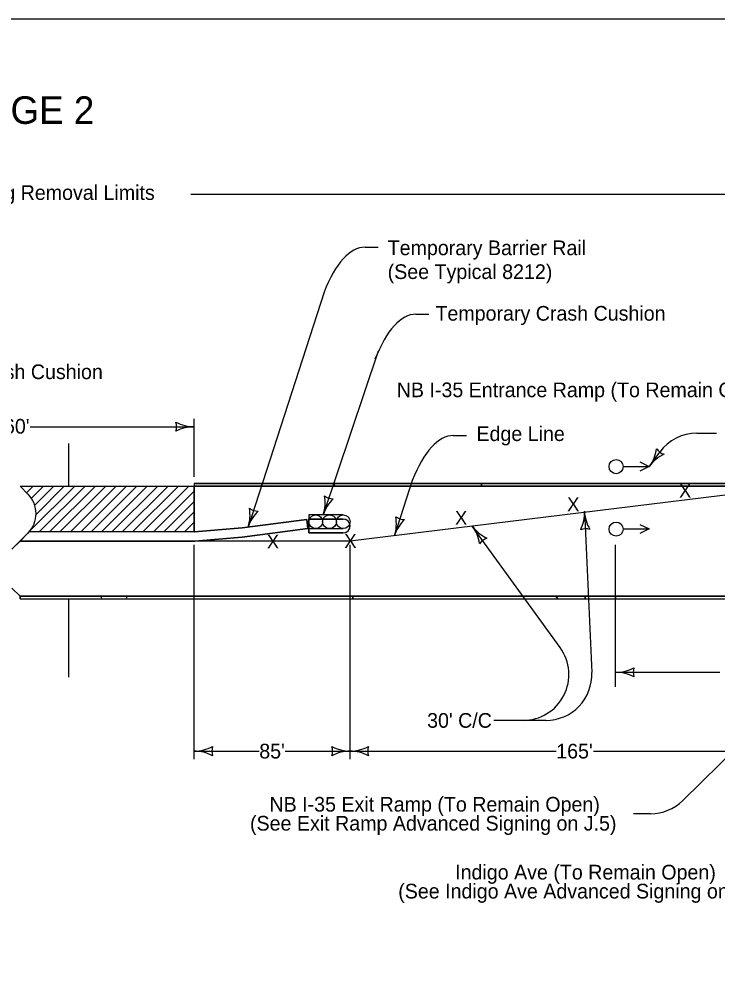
# Model space of a CAD drawing. Extents: x -2134934 to -2122394, y -2139046 to -2137036.
# Drawn here: x -2133366 to -2132604, y -2138064 to -2137036 of the extents above; entities that cross this region are included whole.
import ezdxf

# ---------------------------------------------------------------- set-up
doc = ezdxf.new("R2010")
doc.units = 0
for name, color, linetype in [('Barrier', 7, 'Continuous'), ('BridgeSuperStructureExisting', 7, 'Continuous'), ('Default', 7, 'Continuous'), ('DsnShtInsideBorder', 7, 'Continuous'), ('DsnShtPlotIdentification', 7, 'Continuous'), ('DsnShtPlotShape', 7, 'Continuous')]:
    doc.layers.add(name, color=color, linetype=linetype)

msp = doc.modelspace()

# ---------------------------------------------------------------- linework, layer by layer
at = {"layer": 'BridgeSuperStructureExisting'}
for p, q in [((-2133178, -2137227), (-2132514.4, -2137227)), ((-2132988.2, -2137284.8), (-2132973.9, -2137284.8)), ((-2133032.9, -2137333.9), (-2133115.7, -2137590)), ((-2132932.7, -2137357.9), (-2132918.5, -2137357.9)), ((-2132973.7, -2137398.2), (-2133033.8, -2137576.5)), ((-2133174.4, -2137535.2), (-2133174.4, -2137471.9)), ((-2133353.3, -2137480.5), (-2133174.4, -2137480.5)), ((-2132891.9, -2137490.1), (-2132877.7, -2137490.1)), ((-2132626.2, -2137487.4), (-2132604.9, -2137487.4)), ((-2133311.5, -2137498.8), (-2133311.5, -2137545.2)), ((-2132677.6, -2137523.2), (-2132666.8, -2137508.1)), ((-2132706.7, -2137523.7), (-2132678.8, -2137523.7)), ((-2132936.7, -2137539.2), (-2132956, -2137599.2)), ((-2133355.7, -2137553.9), (-2133364.4, -2137545.2)), ((-2133357.2, -2137552.4), (-2133350, -2137545.2)), ((-2133353.3, -2137593.7), (-2133304.8, -2137545.2)), ((-2133352, -2137558.4), (-2133338.7, -2137545.2)), ((-2133348.3, -2137566.1), (-2133327.4, -2137545.2)), ((-2133346.9, -2137576), (-2133316.1, -2137545.2)), ((-2133343.4, -2137595.2), (-2133293.4, -2137545.2)), ((-2133332.1, -2137595.2), (-2133282.1, -2137545.2)), ((-2133320.8, -2137595.2), (-2133270.8, -2137545.2)), ((-2133309.5, -2137595.2), (-2133259.5, -2137545.2)), ((-2133298.2, -2137595.2), (-2133248.2, -2137545.2)), ((-2133286.9, -2137595.2), (-2133236.9, -2137545.2)), ((-2133275.6, -2137595.2), (-2133225.6, -2137545.2)), ((-2133264.2, -2137595.2), (-2133214.2, -2137545.2)), ((-2133252.9, -2137595.2), (-2133202.9, -2137545.2)), ((-2133241.6, -2137595.2), (-2133191.6, -2137545.2)), ((-2133230.3, -2137595.2), (-2133180.3, -2137545.2)), ((-2133219, -2137595.2), (-2133174.4, -2137550.6)), ((-2133174.4, -2137595.2), (-2133174.4, -2137545.2)), ((-2131862, -2137545.2), (-2133174.4, -2137545.2)), ((-2133174.4, -2137545.2), (-2133174.4, -2137595.2)), ((-2132514.4, -2137545.2), (-2133004.4, -2137605.2)), ((-2133207.7, -2137595.2), (-2133174.4, -2137561.9)), ((-2133196.4, -2137595.2), (-2133174.4, -2137573.2)), ((-2132749, -2137572.6), (-2132740.9, -2137748.3)), ((-2133185.1, -2137595.2), (-2133174.4, -2137584.5)), ((-2133051.7, -2137581.6), (-2133122.2, -2137590.8)), ((-2133122.2, -2137590.8), (-2133051.7, -2137581.6)), ((-2133122.2, -2137590.8), (-2133051.7, -2137581.6)), ((-2133050.4, -2137591.5), (-2133051.7, -2137581.6)), ((-2133051.7, -2137581.6), (-2133050.4, -2137591.5)), ((-2133051.7, -2137581.6), (-2133050.4, -2137591.5)), ((-2133049.4, -2137576.5), (-2133049.4, -2137591.5)), ((-2133011.9, -2137576.5), (-2133049.4, -2137576.5)), ((-2133049.4, -2137596.2), (-2133049.4, -2137581.2)), ((-2133049.4, -2137581.2), (-2133011.9, -2137581.2)), ((-2133174.3, -2137595.2), (-2133354.4, -2137595.2)), ((-2133174.3, -2137595.2), (-2133354.4, -2137595.2)), ((-2133174.4, -2137595.2), (-2133122.2, -2137590.8)), ((-2133122.2, -2137590.8), (-2133174.3, -2137595.2)), ((-2133174.3, -2137595.2), (-2133122.2, -2137590.8)), ((-2133122.3, -2137600.8), (-2133050.4, -2137591.5)), ((-2133050.4, -2137591.5), (-2133122.3, -2137600.8)), ((-2133050.4, -2137591.5), (-2133122.3, -2137600.8)), ((-2133049.4, -2137591.5), (-2133011.9, -2137591.5)), ((-2132775.4, -2137721.3), (-2132871.2, -2137588.8)), ((-2132706.7, -2137591.7), (-2132678.8, -2137591.7)), ((-2133373.2, -2137613.9), (-2133355.7, -2137596.4)), ((-2133355.7, -2137596.4), (-2133364.4, -2137605.2)), ((-2133364.4, -2137605.2), (-2133173.9, -2137605.2)), ((-2133173.9, -2137605.2), (-2133364.4, -2137605.2)), ((-2133173.9, -2137605.2), (-2133364.4, -2137605.2)), ((-2133173.9, -2137605.2), (-2133122.3, -2137600.8)), ((-2133122.3, -2137600.8), (-2133173.9, -2137605.2)), ((-2133122.3, -2137600.8), (-2133173.9, -2137605.2)), ((-2133004.4, -2137605.2), (-2133173.9, -2137605.2)), ((-2133011.9, -2137596.2), (-2133049.4, -2137596.2)), ((-2133174.4, -2137842.8), (-2133174.4, -2137609.3)), ((-2133004.4, -2137842.8), (-2133004.4, -2137609.3)), ((-2132714.9, -2137764.1), (-2132714.9, -2137609.3)), ((-2133364.4, -2137665.2), (-2133373.2, -2137656.4)), ((-2133373.2, -2137656.4), (-2133364.4, -2137665.2)), ((-2133364.4, -2137665.2), (-2131862, -2137665.2)), ((-2133311.5, -2137668.2), (-2133311.5, -2137753.6)), ((-2132641.7, -2137887.9), (-2132453.6, -2137702.6)), ((-2132714.9, -2137748.2), (-2132601.4, -2137748.2)), ((-2132790.9, -2137800.6), (-2132847.6, -2137800.6)), ((-2133174.4, -2137834.1), (-2133103.5, -2137834.1)), ((-2133075.4, -2137834.1), (-2133004.4, -2137834.1)), ((-2133004.4, -2137834.1), (-2132779.7, -2137834.1)), ((-2132739.2, -2137834.1), (-2132514.4, -2137834.1)), ((-2132676.8, -2137902.3), (-2132695.3, -2137902.3))]:
    msp.add_line(p, q, dxfattribs=at)
for points in [[(-2132688.4, -2137518.9), (-2132678.4, -2137523.9), (-2132688.4, -2137528.9)], [(-2133364.4, -2137545.2), (-2133174.4, -2137545.2)], [(-2133354.4, -2137595.2), (-2133354.5, -2137595.1)], [(-2132688.4, -2137586.9), (-2132678.4, -2137591.9), (-2132688.4, -2137596.9)], [(-2133364.4, -2137605.2), (-2133364.4, -2137605.2), (-2133373.2, -2137613.9)]]:
    msp.add_lwpolyline(points, dxfattribs=at)
for centre, radius in [((-2132714.4, -2137524), 7.74), ((-2133041.9, -2137584), 7.5), ((-2133041.9, -2137584), 7.5), ((-2133026.9, -2137584), 7.5), ((-2133026.9, -2137584), 7.5), ((-2133011.9, -2137584), 7.5), ((-2133011.9, -2137584), 7.5), ((-2132714.4, -2137592.1), 7.74)]:
    msp.add_circle(centre, radius, dxfattribs=at)
for centre, radius, start, end in [((-2133210.1, -2137480.5), 16.4, 342.2666, 17.7333), ((-2133174.4, -2137438), 42.5, 241.9275, 270), ((-2133174.4, -2137523), 42.5, 90, 118.0725), ((-2132626.2, -2137537.4), 50, 90, 144.138), ((-2133376.9, -2137575.2), 30, 315, 45), ((-2133011.9, -2137588.7), 7.5, 269.9996, 90), ((-2133376.9, -2137575.2), 30, 315, 318.2713), ((-2132815.9, -2137750.6), 50, 270, 35.862), ((-2132790.9, -2137750.6), 50, 270, 2.6154), ((-2132714.9, -2137705.7), 42.5, 270, 298.0725), ((-2132714.9, -2137790.7), 42.5, 61.9275, 90), ((-2132679.3, -2137748.2), 16.4, 162.2666, 197.7334), ((-2132676.8, -2137852.3), 50, 270, 314.5635)]:
    msp.add_arc(centre, radius, start, end, dxfattribs=at)
for centre in [(-2132988.2, -2137497.7), (-2132932.7, -2137570.8), (-2132891.9, -2137703)]:
    msp.add_ellipse(centre, major_axis=(0, 212.9), ratio=0.328743, start_param=0, end_param=0.693162, dxfattribs=at)
at = {"layer": 'Default'}
msp.add_lwpolyline([(-2134934.4, -2137035.9), (-2131799.4, -2137035.9), (-2131799.4, -2139045.9), (-2134934.4, -2139045.9)], close=True, dxfattribs=at)
at = {"layer": 'DsnShtInsideBorder'}
for p, q in [((-2133011.9, -2137581.2), (-2133049.4, -2137581.2)), ((-2133049.4, -2137581.2), (-2133049.4, -2137596.2)), ((-2133049.4, -2137596.2), (-2133011.9, -2137596.2))]:
    msp.add_line(p, q, dxfattribs=at)
msp.add_arc((-2133011.9, -2137588.7), 7.5, 270.0024, 89.9972, dxfattribs=at)
at = {"layer": 'DsnShtPlotIdentification'}
for p, q in [((-2133174.4, -2137542.2), (-2133174.4, -2137545.2)), ((-2133174.4, -2137542.2), (-2133174.4, -2137545.2)), ((-2133100.2, -2137542.2), (-2133174.4, -2137542.2)), ((-2133100.2, -2137542.2), (-2133101.2, -2137545.2)), ((-2133101.2, -2137545.2), (-2133100.2, -2137542.2)), ((-2133021.1, -2137542.2), (-2133100.2, -2137542.2)), ((-2133021.1, -2137542.2), (-2133022.1, -2137545.2)), ((-2133022.1, -2137545.2), (-2133021.1, -2137542.2)), ((-2132860.7, -2137542.2), (-2133021.1, -2137542.2)), ((-2132860.7, -2137542.2), (-2132861.6, -2137545.2)), ((-2132861.6, -2137545.2), (-2132860.7, -2137542.2)), ((-2132547, -2137542.2), (-2132860.7, -2137542.2)), ((-2133174.4, -2137545.2), (-2133173.7, -2137545.2)), ((-2133173.7, -2137545.2), (-2133101.2, -2137545.2)), ((-2133101.2, -2137545.2), (-2133022.1, -2137545.2)), ((-2133022.1, -2137545.2), (-2132861.6, -2137545.2)), ((-2132861.6, -2137545.2), (-2132568.7, -2137545.2)), ((-2133364.4, -2137668.2), (-2133364.4, -2137665.2)), ((-2133364.4, -2137665.2), (-2131862, -2137665.2)), ((-2133364.4, -2137665.2), (-2131862, -2137665.2)), ((-2133276.3, -2137665.2), (-2133364.4, -2137665.2)), ((-2133364.4, -2137665.2), (-2133364.4, -2137668.2)), ((-2133247.5, -2137665.2), (-2133276.3, -2137665.2)), ((-2133001.5, -2137665.2), (-2133247.5, -2137665.2)), ((-2133001.5, -2137668.2), (-2133001.5, -2137665.2)), ((-2132780.1, -2137665.2), (-2133001.5, -2137665.2)), ((-2133001.5, -2137665.2), (-2133001.5, -2137668.2)), ((-2132778, -2137668.2), (-2132780.1, -2137665.2)), ((-2132780.1, -2137665.2), (-2132778, -2137668.2)), ((-2132748.3, -2137665.2), (-2132780.1, -2137665.2)), ((-2132748.2, -2137668.2), (-2132748.3, -2137665.2)), ((-2132714.9, -2137665.2), (-2132748.3, -2137665.2)), ((-2132748.3, -2137665.2), (-2132748.2, -2137668.2)), ((-2132714.9, -2137668.2), (-2132714.9, -2137665.2)), ((-2132441.1, -2137665.2), (-2132714.9, -2137665.2)), ((-2132714.9, -2137665.2), (-2132714.9, -2137668.2)), ((-2133364.4, -2137668.2), (-2131862, -2137668.2)), ((-2133364.4, -2137668.2), (-2133275.4, -2137668.2)), ((-2133275.4, -2137668.2), (-2133248.5, -2137668.2)), ((-2133248.5, -2137668.2), (-2133001.5, -2137668.2)), ((-2133001.5, -2137668.2), (-2132778, -2137668.2)), ((-2132778, -2137668.2), (-2132748.2, -2137668.2)), ((-2132748.2, -2137668.2), (-2132714.9, -2137668.2)), ((-2132714.9, -2137668.2), (-2132442.1, -2137668.2))]:
    msp.add_line(p, q, dxfattribs=at)
for points in [[(-2133174.4, -2137542.2), (-2131862, -2137542.2)], [(-2133174.4, -2137545.2), (-2131862, -2137545.2)], [(-2133173.7, -2137545.2), (-2131861.3, -2137545.2)]]:
    msp.add_lwpolyline(points, dxfattribs=at)
for start, end in [(191.3299, 203.618), (191.3299, 203.618), (336.382, 348.6701), (336.382, 348.6701)]:
    msp.add_arc((-2133261.9, -2137662.3), 14.7, start, end, dxfattribs=at)
at = {"layer": 'DsnShtPlotShape'}
for centre, radius, start, end in [((-2132712.3, -2137498.5), 42.5, 323.701, 351.7735), ((-2132643.8, -2137548.8), 42.5, 115.6285, 143.701), ((-2132656.9, -2137495), 16.4, 215.9676, 251.4343), ((-2133074.2, -2137563.4), 42.5, 342.0849, 10.1574), ((-2132993.3, -2137589.6), 42.5, 134.0124, 162.0849), ((-2133022.8, -2137542.6), 16.4, 234.3516, 269.8183), ((-2133156.1, -2137576.9), 42.5, 342.0849, 10.1574), ((-2133075.2, -2137603.1), 42.5, 134.0124, 162.0849), ((-2133104.7, -2137556.1), 16.4, 234.3516, 269.8183), ((-2132791.4, -2137574.5), 42.5, 334.5429, 2.6154), ((-2132706.5, -2137570.6), 42.5, 182.6154, 210.6879), ((-2132996.5, -2137586.2), 42.5, 342.0849, 10.1574), ((-2132915.6, -2137612.3), 42.5, 134.0124, 162.0849), ((-2132945.1, -2137565.3), 16.4, 234.3516, 269.8183), ((-2132836.9, -2137563.7), 42.5, 216.299, 244.3715), ((-2132905.4, -2137614), 42.5, 8.2265, 36.299), ((-2132747.3, -2137608.2), 16.4, 74.8821, 110.3488), ((-2132850.1, -2137617.6), 16.4, 108.5657, 144.0324), ((-2133174.4, -2137791.6), 42.5, 270, 298.0725), ((-2133138.8, -2137834.1), 16.4, 162.2666, 197.7334), ((-2133040, -2137834.1), 16.4, 342.2666, 17.7333), ((-2133004.4, -2137791.6), 42.5, 241.9275, 270), ((-2133004.4, -2137791.6), 42.5, 270, 298.0725), ((-2132968.8, -2137834.1), 16.4, 162.2666, 197.7334), ((-2133174.4, -2137876.6), 42.5, 61.9275, 90), ((-2133004.4, -2137876.6), 42.5, 90, 118.0725), ((-2133004.4, -2137876.6), 42.5, 61.9275, 90)]:
    msp.add_arc(centre, radius, start, end, dxfattribs=at)

# ---------------------------------------------------------------- texts
at = {"layer": 'Barrier'}
msp.add_text('STAGE 2', height=30, dxfattribs=at).set_placement((-2133452.8, -2137150.4))
at = {"layer": 'BridgeSuperStructureExisting'}
for s, height, p in [('Pavement Marking Removal Limits', 16, (-2133548, -2137233.3)), ('Temporary Barrier Rail', 16, (-2132963.5, -2137293.5)), ('(See Typical 8212)', 16, (-2132963.5, -2137319.5)), ('Temporary Crash Cushion', 16, (-2132911.4, -2137364.9)), ('Temporary Crash Cushion', 16, (-2133525, -2137428.6)), ('NB I-35 Entrance Ramp (To Remain Open)', 16, (-2132953.6, -2137448.3)), ("460'", 16, (-2133393.8, -2137488)), ('Edge Line', 16, (-2132866.7, -2137496.1)), ('X', 15, (-2133095.3, -2137613.2)), ('X', 15, (-2133010.8, -2137612.6)), ("30' C/C", 16, (-2132920.5, -2137808.6)), ("85'", 16, (-2133103.5, -2137842.1)), ("165'", 16, (-2132779.7, -2137842.1)), ('NB I-35 Exit Ramp (To Remain Open)', 16, (-2133092.4, -2137900)), ('(See Exit Ramp Advanced Signing on J.5)', 16, (-2133113.6, -2137920.7)), ('Indigo Ave (To Remain Open)', 16, (-2132889.9, -2137974)), ('(See Indigo Ave Advanced Signing on J.5)', 16, (-2132952, -2137994.7))]:
    msp.add_text(s, height=height, dxfattribs=at).set_placement(p)
for p in [(-2132645.8, -2137557.8), (-2132767.8, -2137572.6), (-2132890.1, -2137587.4)]:
    msp.add_text('X', height=15, rotation=359.9705, dxfattribs=at).set_placement(p)

doc.saveas('drawing.dxf')
